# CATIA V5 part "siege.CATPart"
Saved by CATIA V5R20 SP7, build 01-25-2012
Part number: siege
Bounding box of the stored display mesh (mm): x 365.397 to 583.079, y -90 to 90, z 327.907 to 582.538
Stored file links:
  D:\thinkmotion-MPB\Dropbox\Pack 1 sylvain\CFAO_2010_yyang\yyang\CFAO_2010_yyang\siege.CATPart
  D:\thinkmotion-MPB\Dropbox\Pack 1 sylvain\CFAO_2010_yyang\yyang\CFAO_2010_yyang\yyang.CATProduct
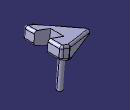
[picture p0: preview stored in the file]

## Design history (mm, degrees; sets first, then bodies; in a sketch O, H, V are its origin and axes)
External parameters (linked from other documents)
  `External.rayon du tube` = 12 mm
  `External.rayon interieur du tube` = 10 mm
  `External.longueur du tube` = 150 mm
  `External.rayon du support` = 15 mm
  `External.position horizontale du pivot2` = 50 mm
  `External.rayon2 du tube2` = 24 mm
  `External.epaisseur du pivot` = 2 mm
  `External.rayon1 de l'antiboue` = 30 mm
  `External.epaisseur de la boite` = 7.5 mm
  `External.rayon1 du tube2` = 21 mm
Set1
  Plane1: linked copy from another document
  Point1: linked copy from another document
  Plane2: linked copy from another document
  Point2: linked copy from another document
  Plane3: linked copy from another document
  Line1: linked copy from another document
  Plane4: linked copy from another document
Body1 (main body)
  Sketch1 on Plane1, origin (1.7869, 0, 286.9252), H (0.9965, 0, 0.0839), V (0, 1, 0)
    circle A1 centre (500.2867, 0) radius 12
    point P1 (500.2867, 0)
    reference projected point E1 (500.2867, 0) from Point1
    reference projected point E2 (500.2867, 0) from Point1
    circle A2 centre (500.2867, 0) radius 10
    point P2 (500.2867, 0)
    reference projected point E3 (500.2867, 0) from Point1
    reference projected point E4 (500.2867, 0) from Point1
    distance A1 E2 = 12 {= `External.rayon du tube`}
    distance A2 E4 = 10 {= `External.rayon interieur du tube`}
    coincidence: P1 E1, P2 E3
  Pad1: profile Sketch1, direction (-0.0839, 0, 0.9965), length 150 {= `External.longueur du tube`}
  Sketch2 on Plane2, origin (1.7619, 0, 457.525), H (0.9965, 0, 0.0839), V (0, 1, 0)
    circle A1 centre (485.9931, 0) radius 15
    point P1 (485.9931, 0)
    reference projected point E1 (485.9931, 0) from Point2
    reference projected point E2 (485.9931, 0) from Point1
    distance A1 E2 = 15 {= `External.rayon du support`}
    coincidence: P1 E1
  Pad2: profile Sketch2, direction (0.0839, 0, -0.9965), up to end face of Pad1
  Sketch3 on Plane3, origin (0, 0, 0), H (-1, 0, 0), V (0, 0, 1)
    point P1 (-530.8815, 502.0914)
    line L1 (-530.8815, 502.0914) -> (-366.4637, 488.2429)
    line L2 (-366.4637, 488.2429) -> (-364.7851, 508.1723)
    point P3 (-364.7851, 508.1723)
    line L3 (-364.7851, 508.1723) -> (-578.973, 586.4253)
    point P4 (-578.973, 586.4253)
    line L4 (-578.973, 586.4253) -> (-583.5892, 531.6194)
    point P5 (-583.5892, 531.6194)
    line L5 (-583.5892, 531.6194) -> (-530.8815, 502.0914)
    reference intersected line E1 through (-1.7619, 457.525) direction (-0.9965, 0.0839) from Plane2
    reference projected line E2 (-486.0403, 498.3145) -> (-500.3084, 328.9144) from Line1
    reference projected line E3 (-486.0403, 498.3145) -> (-500.3084, 328.9144) from Line1
    length L2 = 20
    distance P3 E2 = 120
    distance P4 E3 = 100
    length L4 = 55
    distance P1 L4 = 55
    distance P5 L1 = 25
    coincidence: L1 E1
    perpendicularity: L2 L1, L4 L1
  Sketch4 on Plane2, origin (1.7619, 0, 457.525), H (0.9965, 0, 0.0839), V (0, 1, 0)
    point P1 (585.9931, -90)
    line L1 (585.9931, -90) -> (585.9931, 90)
    point P2 (585.9931, 90)
    line L2 (585.9931, 90) -> (545.9931, 90)
    line L3 (545.9931, 90) -> (365.9931, 10)
    line L4 (365.9931, 10) -> (365.9931, -10)
    point P5 (365.9931, -10)
    line L5 (365.9931, -10) -> (545.9931, -90)
    line L6 (545.9931, -90) -> (585.9931, -90)
    point P7 (585.9931, -90)
    reference intersected line E1 through (0, 0) direction (-1, 0) from Plane3
    reference projected point E2 (585.9931, 0) from vertex [element of Sketch3 | element of Sketch3]
    reference projected point E3 (365.9931, 0) from vertex [element of Sketch3 | element of Sketch3]
    reference intersected line E4 through (0, 0) direction (-1, 0) from Plane3
    length L1 = 180
    distance E1 P2 = 90
    length L4 = 20
    distance P5 E4 = 10
    length L6 = 40
    length L2 = 40
    vertical: L1 V, L4 V
    horizontal: L2 H, L6 H
    coincidence: P7 L1, P1 P7, L1 E2, L4 E3
  SolidCombine1: FirstComponentDirection Sketch3, FirstComponentProfile Sketch3, SecondComponentDirection Sketch4, SecondComponentProfile Sketch4
  Fillet1: radius 10, on face of SolidCombine1 from Sketch3.L3; face of SolidCombine1 from Sketch4.L5; face of SolidCombine1 from Sketch4.L4; face of SolidCombine1 from Sketch4.L3; face of SolidCombine1 from Sketch3.L5; face of SolidCombine1 from Sketch3.L1; face of SolidCombine1 from Sketch4.L2; face of SolidCombine1 from Sketch4.L1
  Sketch5 on Plane3, origin (0, 0, 0), H (-1, 0, 0), V (0, 0, 1)
    line L1 (-578.973, 586.4253) -> (-504.9808, 559.3925)
    line L2 (-504.9808, 559.3925) -> (-509.9556, 500.3289)
    line L3 (-509.9556, 500.3289) -> (-585.6874, 506.7076)
    line L4 (-585.6874, 506.7076) -> (-578.973, 586.4253)
    reference projected arc E1 centre (-570.1072, 572.5397) radius 10 from (-567.8025, 582.2705) to (-580.1072, 572.5397) ccw from edge [face of Fillet1 | face of Fillet1]
    reference projected line E2 (-584.0752, 525.8491) -> (-581.9279, 551.3435) from edge [face of Fillet1 | face of SolidCombine1 from Sketch4.L1]
    reference projected line E3 (-548.8988, 503.609) -> (-421.2765, 492.8597) from edge [face of SolidCombine1 from Sketch3.L1 | face of Fillet1]
    reference projected line E4 (-486.0403, 498.3145) -> (-500.3084, 328.9144) from Line1
    reference projected line E5 (-486.0403, 498.3145) -> (-500.3084, 328.9144) from Line1
    reference projected line E6 (-525.2159, 501.6142) -> (-397.5936, 490.8649) from edge [face of SolidCombine1 from Sketch3.L1 | face of Fillet1]
    reference projected line E7 (-555.6763, 577.9139) -> (-529.1317, 568.2159) from edge [face of Fillet1 | face of SolidCombine1 from Sketch3.L3]
    distance L2 E4 = 24 {= `External.position horizontale du pivot2`-`External.rayon2 du tube2`-`External.epaisseur du pivot`}
    tangency: L1 E1
    coincidence: L4 E2, L3 E3, L1 E7
    parallelism: L2 E5, L3 E6
  Pocket1: profile Sketch5, direction (0, -1, 0), length 37.5 {= `External.rayon1 de l'antiboue`+`External.epaisseur de la boite`}, opposite side length 26 {= `External.epaisseur du pivot`+`External.rayon2 du tube2`}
